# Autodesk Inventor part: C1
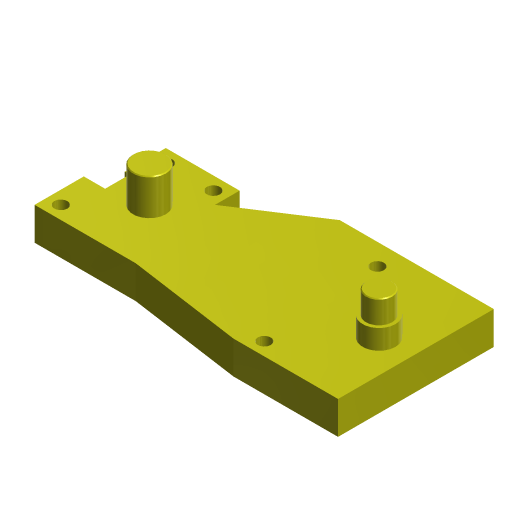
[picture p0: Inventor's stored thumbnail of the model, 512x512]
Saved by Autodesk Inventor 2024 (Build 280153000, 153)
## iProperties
Company: ATC
Shininess: 20.0
Angle Display Precision: 2
Document Length Units: 11269
Document Angle Units: 11279
Document Time Units: 11290
Document Mass Units: 11283
Document Length Units Precision: 3
Document Angle Units Precision: 2
Created: 2023-03
Part Number: C1
Material: Kurs-AJ
Document SubType Name: Modelowanie
Designer: Andrzej Jaskulski
Density: 1 g/cm^3
Appearance: Żółta
Checked By: A.J.
Engr Approved By: Andrzej Jaskulski
Mfg Approved By: Andrzej Jaskulski
Authority: A.J.
Density: 0.0
Volumn: 0.0
Area: 0.0
PropertySet Name: Model Information
Control State: 0
Master: False
Checked Out: False
Title: A.J.: Kurs R2024-MEP
Author: Andrzej Jaskulski
Revision Number: 1/24
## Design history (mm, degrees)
node "Bryła1"
node "Korpusy bryłowe"
node "Korpusy powierzchniowe"
node "Początek"
sketch "Szkic1"
  geometry: L1 (60, 60)-(60, 90); L2 (60, 90)-(73, 90) reference; L3 (73, 90)-(73, 105) reference; L4 (73, 105)-(70, 105) reference; L5 (70, 105)-(70, 130) reference; L6 (70, 130)-(115, 130) reference; L7 (115, 130)-(115, 115) reference; L8 (115, 115)-(161.127, 144.955); L9 (161.127, 144.955)-(255, 144.955); L10 (60, 60)-(121.629, 60) reference; L11 (121.629, 60)-(191.251, 50) reference; L12 (191.251, 50)-(255, 50) reference; L13 (255, 50)-(255, 144.955); L14 (95, 95)-(235, 95); C1 r 10 at (95, 95); C2 r 4 at (68, 68); C3 r 4 at (78, 122); C4 r 4 at (197, 131.955); C5 r 4 at (202, 58); C6 r 4 at (107, 122); C7 r 10 at (235, 95); A1 r 40 centre (235, 95) between (205.142, 121.617) and (210.142, 63.662)
  constraints: 28 end point, 8 centre point, 6 horizontal, 4 vertical, 2 coincident, 2 perpendicular, 2 point on circle, 1 horizontal alignment, 1 vertical alignment, 1 other
  dimensions: "d0" = 20 diameter of C1; "d5" = 10 distance between parallel lines of L5 L1; "d6" = 8 diameter of C3; "d7" = 8 diameter of C6 (= d6); "d8" = 8 diameter of C2 (= d6); "d9" = 8 diameter of C4 (= d6); "d10" = 8 diameter of C5 (= d6); "d11" = 8 distance from line of L6 C3.centre; "d12" = 8 distance from line of C3.centre L5 (= d11); "d13" = 8 distance from line of C6.centre L7 (= d11); "d14" = 8 distance from line of C2.centre L10 (= d11); "d15" = 8 distance from line of C2.centre L1 (= d11); "d20" = 35 distance from line of L10 L14.start; "d21" = 35 distance from line of L1 L14.start (= d20); "d22" = 40 radius of A1; "d25" = 20 diameter of C7 (= d0); "d26" = 20 distance from line of A1.centre L13; "d54" = 90 horizontal distance of C4.centre C6.centre; "d55" = 134 horizontal distance of C5.centre C2.centre; "d56" = 13 distance from line of L9 C4.centre; "d57" = 8 distance from line of C5.centre L12; "d58" = 140 distance of L14.start L14.end; "d59" = 15 distance of L6.end L7.end; "d60" = 55 distance of L7.end L8.end; "d61" = 57 deg angle of L7 L8
extrude "Wyciągnięcie proste1" new body sketch "Szkic1" distance "d1" = 20; taper "d2" = 0 deg
extrude "Wyciągnięcie proste2" join sketch "Szkic1" distance "d27" = 12; taper "d28" = 0 deg
sketch "Szkic2"
  geometry: C1 r 10 at (0, 0) reference; C2 r 8 at (0, 0)
  constraints: 1 centre point, 1 coincident
  dimensions: "d34" = 2 radial gap between concentric circles of C2 C1
extrude "Wyciągnięcie proste3" join sketch "Szkic2" distance "d35" = 14; taper "d36" = 0 deg
chamfer "Faza1" distance "d39" = 0.5; stored, may be unused: second distance "d40" = 0.5, angle "d64" = 45 deg
extrude "Wyciągnięcie proste5" join sketch "Szkic1" distance "d46" = 22; taper "d47" = 0 deg
chamfer "Faza2" distance "d48" = 0.5; stored, may be unused: second distance "d49" = 0.5, angle "d65" = 45 deg
node "Płaszczyzna konstrukcyjna3"
sketch "Tory Suwaków"
  geometry: L1 (-51.051, 35)-(275, 35); L2 (121.629, 60)-(60, 60) reference; L3 (275, 35)-(275, 245.91); L4 (255, 144.955)-(255, 50) reference
  constraints: 4 end point, 1 horizontal, 1 perpendicular
  dimensions: "d62" = 25 distance between parallel lines of L2 L1; "d63" = 20 distance between parallel lines of L4 L3
node "Płaszczyzna YZ"
node "Płaszczyzna XZ"
node "Płaszczyzna XY"
node "Oś X"
node "Oś Y"
node "Oś Z"
node "Punkt środkowy"
other parameters: "d29" = 0, "d30" = 0, "d31" = 0, "d32" = 0, "d33" = 0, "d50" = 6
